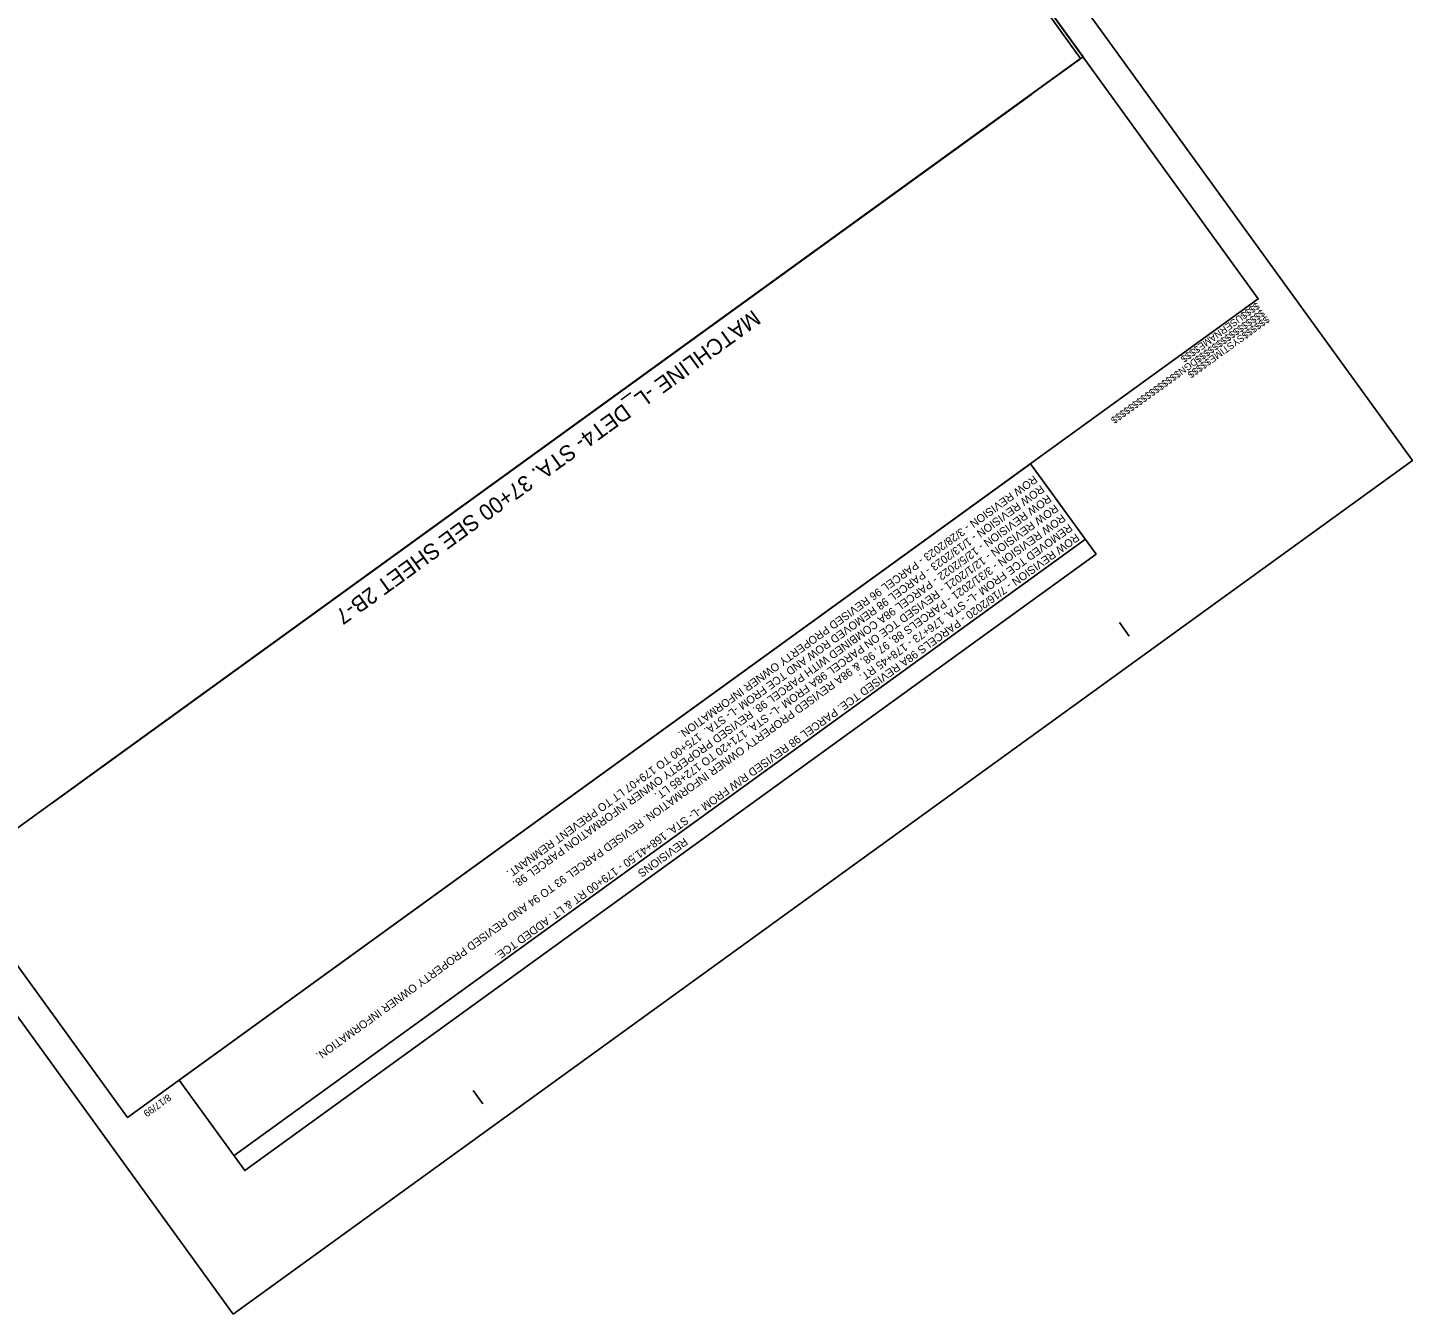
# Model space of a CAD drawing. Extents: x 474248 to 476123, y 501895 to 503900.
# Drawn here: x 475081 to 476123, y 501895 to 502862 of the extents above; entities that cross this region are included whole.
import ezdxf

# ---------------------------------------------------------------- set-up
doc = ezdxf.new("R2010")
doc.units = 0
for name, color, linetype in [('Matchline', 7, 'Continuous'), ('Matchline Text', 7, 'Continuous'), ('Scratch_Level_5', 7, 'Continuous'), ('Sheet Block Revision CELL', 7, 'Continuous'), ('Sheet Layout Plan Border', 7, 'Continuous'), ('Sheet Plan CELL', 7, 'Continuous'), ('Sheet Plot Border Outside CELL', 7, 'Continuous')]:
    doc.layers.add(name, color=color, linetype=linetype)

msp = doc.modelspace()

# ---------------------------------------------------------------- linework, layer by layer
at = {"layer": 'Matchline'}
msp.add_line((475836.4, 502812.6), (475099.9, 502279.5), dxfattribs=at)
at = {"layer": 'Scratch_Level_5'}
msp.add_lwpolyline([(475148.8, 502314.9), (475799.7, 502786.1), (475873.1, 502839.2), (475223.6, 503740.2), (475493.2, 503367.9), (474627.9, 502772.5), (475024.4, 502224.9)], close=True, dxfattribs=at)
at = {"layer": 'Sheet Block Revision CELL'}
msp.add_line((475876.8, 502477.7), (475236.4, 502014), dxfattribs=at)
msp.add_lwpolyline([(475884.9, 502466.5), (475244.5, 502002.8), (475195.2, 502070.8), (475835.6, 502534.5)], close=True, dxfattribs=at)
at = {"layer": 'Sheet Layout Plan Border'}
msp.add_lwpolyline([(475148.8, 502314.9), (475799.7, 502786.1), (475875, 502840.6), (475397.5, 503499.9), (475353.9, 503468.3), (475265.2, 503590.8), (475283.7, 503604.1), (475199.9, 503719.8), (475161.6, 503692), (475161.6, 503692), (475161.6, 503692), (475161.6, 503692), (475161.6, 503692), (475063.5, 503827.5), (474417.2, 503359.4), (474534.5, 503197.4), (474393.9, 503095.6), (475024.4, 502224.9)], close=True, dxfattribs=at)
at = {"layer": 'Sheet Plan CELL'}
for p, q in [((476006.8, 502658.5), (476006.8, 502658.5)), ((475909.6, 502404.8), (475902.3, 502415)), ((475423.6, 502052.9), (475416.3, 502063)), ((475156.3, 502042.7), (475156.3, 502042.7))]:
    msp.add_line(p, q, dxfattribs=at)
for points in [[(474276.6, 503257.7), (475156.3, 502042.7), (476006.8, 502658.5), (475127.1, 503873.5)], [(476006.8, 502658.5), (475156.4, 502042.7), (474393.9, 503095.6), (474515.4, 503183.6), (474398.1, 503345.7), (475127.1, 503873.5)]]:
    msp.add_lwpolyline(points, close=True, dxfattribs=at)
at = {"layer": 'Sheet Plot Border Outside CELL'}
msp.add_lwpolyline([(475235.7, 501894.7), (474248.4, 503258.2), (475135.3, 503900.4), (476122.7, 502536.9)], close=True, dxfattribs=at)

# ---------------------------------------------------------------- texts
at = {"layer": 'Matchline Text'}
msp.add_text('MATCHLINE -L_DET4- STA. 37+00 SEE SHEET 2B-7', height=12, rotation=215.901, dxfattribs=at).set_placement((475626.7, 502650.8))
at = {"layer": 'Sheet Block Revision CELL'}
for s, p in [('ROW REVISION - 3/28/2023 - PARCEL 96 REVISED PROPERTY OWNER INFORMATION. ', (475837.9, 502526.1)), ('ROW REVISION - 1/13/2023 - PARCEL 98 REMOVED ROW AND TCE FROM -L- STA.  175+00 TO 179+07 LT TO PREVENT REMNANT.', (475843.1, 502518.8)), ('ROW REVISION - 12/5/2022 - PARCEL 98A COMBINED WITH PARCEL 98. REVISED PROPERTY OWNER INFORMATION PARCEL 98. ', (475848.4, 502511.6)), ('ROW REVISION - 12/1/2021 - REVISED TCE ON PARCEL 98A FROM -L- STA. 171+20 TO 172+85 LT. ', (475853.7, 502504.3)), ('ROW REVISION - 3/31/2021 - PARCELS 88, 97, 98, & 98A REVISED PROPERTY OWNER INFORMATION. REVISED PARCEL 93 TO 94 AND REVISED PROPERTY OWNER INFORMATION.', (475859, 502497)), ('ROW REVISION - 7/16/2020 - PARCELS 98A REVISED TCE. PARCEL 98 REVISED R/W FROM -L- STA. 168+41.50 - 179+00 RT & LT. ADDED TCE.', (475869.5, 502482.4)), ('REMOVED TCE FROM -L- STA. 176+73 - 178+45 RT.', (475864.3, 502489.7)), ('REVISIONS', (475574.9, 502253.5))]:
    msp.add_text(s, height=6, rotation=215.9074, dxfattribs=at).set_placement(p)
at = {"layer": 'Sheet Plan CELL'}
for s, p in [('$$$$$$$$$$$$$$$$DGN$$$$$$$$$$$$$$$$', (476009.3, 502650.9)), ('$$$$USERNAME$$$$', (476005.5, 502656.2)), ('$$$$$$SYSTIME$$$$$', (476012.9, 502646)), ('8/17/99', (475186.7, 502060.7))]:
    msp.add_text(s, height=5.25, rotation=215.9074, dxfattribs=at).set_placement(p)

doc.saveas('drawing.dxf')
